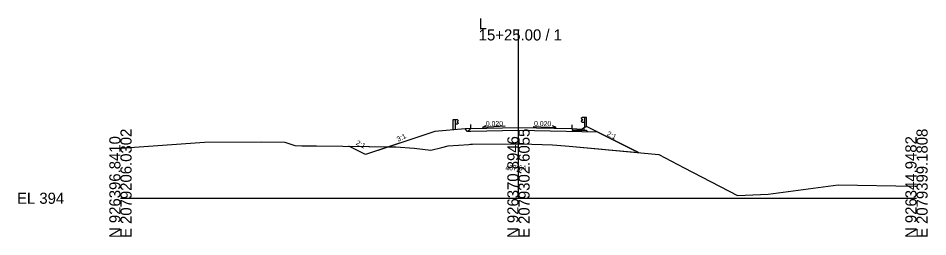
# Model space of a CAD drawing. Extents: x -26 to 10503, y -10 to 9546.
# Drawn here: x 974.3 to 1202.8, y 490.3 to 545.3 of the extents above; entities that cross this region are included whole.
import ezdxf

# ---------------------------------------------------------------- set-up
doc = ezdxf.new("R2010")
doc.units = 0
for name, color, linetype in [('Default', 7, 'Continuous'), ('Exist XS Center Line Elevation Label', 7, 'Continuous'), ('Exist XS Ground Line', 7, 'Continuous'), ('Old_Level_3', 7, 'Continuous'), ('Old_Level_58', 7, 'Continuous'), ('Old_Level_63', 7, 'Continuous'), ('Prop XS Dump Level', 7, 'Continuous'), ('Prop XS EOT Tick Mark', 7, 'Continuous'), ('Prop XS Finish Grade', 7, 'Continuous'), ('Prop XS Finish Grade CurbGutter', 7, 'Continuous'), ('Prop XS Finish Grade Earthwork', 7, 'Continuous'), ('Prop XS Finish Grade Pavement', 7, 'Continuous'), ('Prop XS Pvmt Edge Slope', 7, 'Continuous'), ('Prop XS SE Text', 7, 'Continuous'), ('Prop XS Side Slope Text', 7, 'Continuous'), ('Prop XS Subgrade CurbGutter', 7, 'Continuous'), ('Prop XS Subgrade Earthwork', 7, 'Continuous')]:
    doc.layers.add(name, color=color, linetype=linetype)

msp = doc.modelspace()

# ---------------------------------------------------------------- linework, layer by layer
at = {"layer": 'Default'}
for points in [[(1119.9, 516.61), (1100, 517.01), (1088, 516.77), (1087.23, 516.75), (1086.58, 517.41), (1078.99, 516.8), (1067.43, 512.94), (1069.22, 512.92), (1073.83, 512.6), (1077.95, 512.12), (1080.71, 512.76), (1082.36, 513.16), (1087.56, 513.52), (1087.92, 513.55), (1088.48, 513.55), (1098.76, 513.67), (1100, 513.64), (1103.37, 513.56), (1108.51, 513.44), (1109.6, 513.38), (1112.73, 513.1), (1130.19, 511.47)], [(1067.43, 512.94), (1061.6, 511), (1057.41, 513.09)]]:
    msp.add_lwpolyline(points, close=True, dxfattribs=at)
at = {"layer": 'Exist XS Ground Line'}
for p, q in [((1000, 512.62), (1021.1, 514.12)), ((1021.1, 514.12), (1035.43, 514.15)), ((1035.43, 514.15), (1041.26, 514.12)), ((1041.26, 514.12), (1043.8, 513.26)), ((1043.8, 513.26), (1045.56, 513.17)), ((1045.56, 513.17), (1049.23, 513.21)), ((1049.23, 513.21), (1069.22, 512.92)), ((1069.22, 512.92), (1073.83, 512.6)), ((1073.83, 512.6), (1077.95, 512.12)), ((1077.95, 512.12), (1080.71, 512.76)), ((1080.71, 512.76), (1082.36, 513.16)), ((1082.36, 513.16), (1087.56, 513.52)), ((1087.56, 513.52), (1087.92, 513.55)), ((1087.92, 513.55), (1088.48, 513.55)), ((1088.48, 513.55), (1098.76, 513.67)), ((1098.76, 513.67), (1100, 513.64)), ((1100, 513.64), (1103.37, 513.56)), ((1103.37, 513.56), (1108.51, 513.44)), ((1108.51, 513.44), (1109.6, 513.38)), ((1109.6, 513.38), (1112.73, 513.1)), ((1112.73, 513.1), (1135.3, 510.99)), ((1135.3, 510.99), (1141.6, 507.62)), ((1141.6, 507.62), (1155, 500.66)), ((1162.77, 501.03), (1180.28, 503.35)), ((1180.28, 503.35), (1199.64, 503.04)), ((1199.64, 503.04), (1200, 503.04)), ((1155, 500.66), (1162.77, 501.03))]:
    msp.add_line(p, q, dxfattribs=at)
at = {"layer": 'Old_Level_3'}
for p, q in [((1083.59, 517.25), (1083.59, 519.75)), ((1083.59, 519.75), (1084.09, 519.75)), ((1084.09, 519.75), (1084.09, 517.25)), ((1084.09, 519.75), (1084.59, 519.75)), ((1084.59, 519.75), (1084.88, 519.55)), ((1084.88, 519.43), (1084.59, 519.23)), ((1084.59, 519.23), (1084.59, 519.14)), ((1084.59, 519.14), (1084.88, 518.94)), ((1084.88, 518.82), (1084.59, 518.62)), ((1084.88, 519.55), (1084.91, 519.49)), ((1084.91, 519.49), (1084.88, 519.43)), ((1084.88, 518.94), (1084.91, 518.88)), ((1084.91, 518.88), (1084.88, 518.82)), ((1115.76, 520.08), (1115.73, 520.02)), ((1115.73, 520.02), (1115.76, 519.96)), ((1115.76, 519.46), (1115.73, 519.4)), ((1115.73, 519.4), (1115.76, 519.34)), ((1116.05, 520.28), (1115.76, 520.08)), ((1115.76, 519.96), (1116.05, 519.76)), ((1116.05, 519.66), (1115.76, 519.46)), ((1115.76, 519.34), (1116.05, 519.14)), ((1116.55, 520.28), (1116.05, 520.28)), ((1116.05, 519.76), (1116.05, 519.66)), ((1116.05, 519.14), (1116.55, 519.14)), ((1117.05, 520.28), (1116.55, 520.28)), ((1116.55, 520.28), (1116.55, 517.76)), ((1117.05, 518.01), (1117.05, 520.28)), ((1084.59, 518.62), (1084.09, 518.62))]:
    msp.add_line(p, q, dxfattribs=at)
at = {"layer": 'Old_Level_63'}
for p, q in [((1100, 500), (1100, 542.45)), ((1000, 500), (1100, 500)), ((1100, 500), (1200, 500))]:
    msp.add_line(p, q, dxfattribs=at)
at = {"layer": 'Prop XS EOT Tick Mark'}
for p, q in [((1088, 517.52), (1088, 518.52)), ((1113.47, 517.49), (1113.47, 518.49))]:
    msp.add_line(p, q, dxfattribs=at)
at = {"layer": 'Prop XS Finish Grade'}
for p, q in [((1088, 517.52), (1086.58, 517.41)), ((1116.49, 517.74), (1117.07, 518.03)), ((1119.9, 516.61), (1117.07, 518.03))]:
    msp.add_line(p, q, dxfattribs=at)
at = {"layer": 'Prop XS Finish Grade CurbGutter'}
for p, q in [((1113.47, 517.49), (1115.8, 517.4)), ((1115.8, 517.4), (1116.49, 517.74))]:
    msp.add_line(p, q, dxfattribs=at)
at = {"layer": 'Prop XS Finish Grade Earthwork'}
for p, q in [((1078.99, 516.8), (1061.6, 511)), ((1086.58, 517.41), (1078.99, 516.8)), ((1119.9, 516.61), (1130.19, 511.47)), ((1061.6, 511), (1057.41, 513.09))]:
    msp.add_line(p, q, dxfattribs=at)
at = {"layer": 'Prop XS Finish Grade Pavement'}
for p, q in [((1088, 517.52), (1100, 517.76)), ((1100, 517.76), (1113.47, 517.49))]:
    msp.add_line(p, q, dxfattribs=at)
at = {"layer": 'Prop XS Pvmt Edge Slope'}
for p, q in [((1088, 517.52), (1087.23, 516.75)), ((1116.49, 517.07), (1116.99, 517.07)), ((1116.99, 517.07), (1117.4, 516.66))]:
    msp.add_line(p, q, dxfattribs=at)
at = {"layer": 'Prop XS SE Text'}
for points in [[(1096.68, 518.08), (1090.93, 517.8), (1091.78, 518.26)], [(1103.68, 518.06), (1109.44, 517.78), (1108.58, 518.24)]]:
    msp.add_lwpolyline(points, dxfattribs=at)
at = {"layer": 'Prop XS Subgrade CurbGutter'}
for p, q in [((1113.47, 517.49), (1113.47, 517.07)), ((1113.47, 517.07), (1116.49, 517.07)), ((1116.49, 517.07), (1116.49, 517.74))]:
    msp.add_line(p, q, dxfattribs=at)
at = {"layer": 'Prop XS Subgrade Earthwork'}
for p, q in [((1087.23, 516.75), (1086.58, 517.41)), ((1088, 516.77), (1087.23, 516.75)), ((1100, 517.01), (1088, 516.77)), ((1119.9, 516.61), (1100, 517.01))]:
    msp.add_line(p, q, dxfattribs=at)

# ---------------------------------------------------------------- texts
at = {"layer": 'Exist XS Center Line Elevation Label'}
msp.add_text('407.64', height=1.25, rotation=360, dxfattribs=at).set_placement((1096.7, 507.01))
at = {"layer": 'Old_Level_58'}
for p in [(1083.96, 517.25), (1116.55, 517.78)]:
    msp.add_text('Case1', height=0.04, dxfattribs=at).set_placement(p)
at = {"layer": 'Old_Level_63'}
for s, p in [('L', (1090, 542.45)), ('15+25.00 / 1', (1090, 539.65)), ('EL 394', (974, 498.6))]:
    msp.add_text(s, height=2.8, dxfattribs=at).set_placement(p)
for s, p in [('E 2079206.0302', (1002.8, 490)), ('E 2079302.6055', (1102.8, 490)), ('E 2079399.1808', (1202.8, 490)), ('N 926396.8410', (1000, 490)), ('N 926370.8946', (1100, 490)), ('N 926344.9482', (1200, 490))]:
    msp.add_text(s, height=2.8, rotation=90, dxfattribs=at).set_placement(p)
at = {"layer": 'Prop XS Dump Level'}
msp.add_text('Case1', height=0.04, dxfattribs=at).set_placement((1080, 516.84))
at = {"layer": 'Prop XS SE Text'}
for rotation, p in [(1.1458, (1091.81, 518.1)), (358.8542, (1103.91, 518.18))]:
    msp.add_text('0.020', height=1.25, rotation=rotation, dxfattribs=at).set_placement(p)
at = {"layer": 'Prop XS Side Slope Text'}
for s, rotation, p in [('2:1', 333.4349, (1122.09, 515.82)), ('2:1', 333.4349, (1059.04, 513.53)), ('3:1', 26.5651, (1069.77, 514.17))]:
    msp.add_text(s, height=1.25, rotation=rotation, dxfattribs=at).set_placement(p)

doc.saveas('drawing.dxf')
